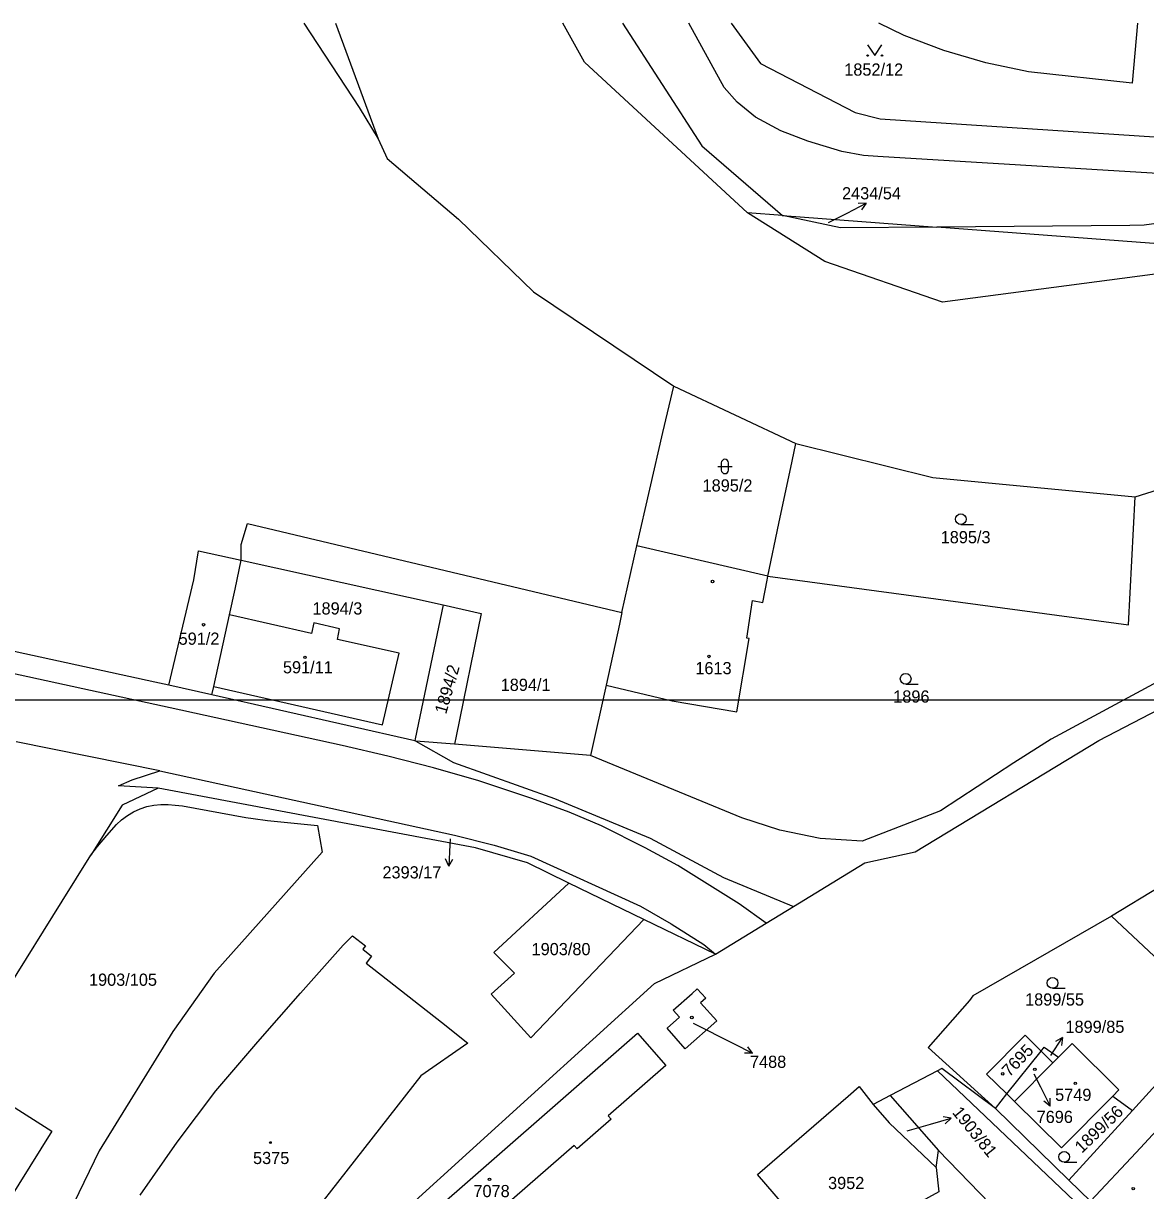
# Model space of a CAD drawing. Extents: x -667048 to -665920, y -1108425 to -1107247.
# Drawn here: x -666539 to -666382.5, y -1107411.8 to -1107249 of the extents above; entities that cross this region are included whole.
import ezdxf

# ---------------------------------------------------------------- set-up
doc = ezdxf.new("R2010")
doc.units = 0
for name, color, linetype in [('Default', 7, 'Continuous'), ('Hranice parcel', 7, 'Continuous'), ('Parcelní čísla', 7, 'Continuous'), ('Pop_ PČ_ popisy', 7, 'Continuous'), ('Vrstva 2', 7, 'Continuous'), ('Značky budov', 7, 'Continuous'), ('Značky kultur', 7, 'Continuous')]:
    doc.layers.add(name, color=color, linetype=linetype)

# ---------------------------------------------------------------- blocks, each defined once
blk = doc.blocks.new('3.041')
at = {"layer": 'Default'}
blk.add_line((8, 0), (1758, 0), dxfattribs=at)
blk.add_circle((8, 750), 750, dxfattribs=at)
blk = doc.blocks.new('4.021')
at = {"layer": 'Default'}
blk.add_circle((-7, 1), 175, dxfattribs=at)
blk = doc.blocks.new('3.161')
at = {"layer": 'Default'}
for p, q in [((-1000, 1000), (1000, 1000)), ((-500, 1500), (-500, 500)), ((500, 500), (500, 1500))]:
    blk.add_line(p, q, dxfattribs=at)
for centre, start, end in [((0, 1500), 0, 180), ((0, 500), 180, 359.98789)]:
    blk.add_arc(centre, 500, start, end, dxfattribs=at)
blk = doc.blocks.new('3.141')
at = {"layer": 'Default'}
blk.add_lwpolyline([(-1000, 1500), (0, 0), (1000, 1500)], dxfattribs=at)
for centre in [(-1000, 0), (1000, 0)]:
    blk.add_circle(centre, 100, dxfattribs=at)
blk = doc.blocks.new('10291')
at = {"layer": 'Default'}
for p, q in [((0, 3001), (-500, 2001)), ((0, 1), (0, 3001)), ((0, 3001), (500, 2001))]:
    blk.add_line(p, q, dxfattribs=at)

msp = doc.modelspace()

# ---------------------------------------------------------------- linework, layer by layer
at = {"layer": 'Hranice parcel'}
for points in [[(-666499.9, -1107248.98), (-666492.15, -1107260.74)], [(-666495.48, -1107248.98), (-666489.54, -1107265.1)], [(-666438.01, -1107275.44), (-666460.74, -1107254.42), (-666463.77, -1107248.98)], [(-666455.44, -1107248.98), (-666444.37, -1107266.08), (-666433.14, -1107275.81)], [(-666356.11, -1107248.98), (-666356.28, -1107250.97), (-666357.81, -1107254.28), (-666361.3, -1107259.67), (-666363.57, -1107262.67), (-666366, -1107265.03), (-666368.53, -1107266.73), (-666371.2, -1107267.99), (-666374.12, -1107268.93), (-666378.04, -1107269.78), (-666380.05, -1107269.97), (-666419.83, -1107267.58), (-666421.83, -1107267.43), (-666424.83, -1107266.88), (-666429.61, -1107265.42), (-666433.36, -1107263.97), (-666436.88, -1107262.08), (-666439.47, -1107259.99), (-666441.27, -1107257.94), (-666446.21, -1107248.98)], [(-666440.27, -1107248.98), (-666436.2, -1107254.59), (-666423.01, -1107261.41), (-666419.51, -1107262.32), (-666380.56, -1107264.87), (-666364.99, -1107248.98)], [(-666383.61, -1107248.98), (-666384.36, -1107257.34), (-666398.82, -1107255.76), (-666404.76, -1107254.5), (-666410.62, -1107252.78), (-666416.15, -1107250.68), (-666419.67, -1107248.98)], [(-666492.15, -1107260.74), (-666489.54, -1107265.1)], [(-666240.48, -1107268.47), (-666267.99, -1107262.05), (-666298.27, -1107263.82), (-666324.76, -1107267.93), (-666375.17, -1107280.18), (-666411.62, -1107277.43)], [(-666489.54, -1107265.1), (-666488.25, -1107267.83)], [(-666227.09, -1107271.48), (-666227.91, -1107279.13), (-666239, -1107270.86), (-666282.86, -1107265.92), (-666341.26, -1107274.38), (-666358.21, -1107280.96), (-666410.8, -1107287.9), (-666427.23, -1107282.22), (-666438.01, -1107275.44)], [(-666488.25, -1107267.83), (-666478.32, -1107276.31), (-666467.85, -1107286.44), (-666448.3, -1107299.6)], [(-666433.14, -1107275.81), (-666438.01, -1107275.44)], [(-666433.14, -1107275.81), (-666411.62, -1107277.43)], [(-666411.62, -1107277.43), (-666425.05, -1107277.51), (-666433.14, -1107275.81)], [(-666380.65, -1107276.85), (-666382.68, -1107277.12), (-666384.67, -1107277.21), (-666411.62, -1107277.43)], [(-666453.46, -1107321.86), (-666449.8, -1107306.06), (-666448.3, -1107299.6)], [(-666448.3, -1107299.6), (-666431.28, -1107307.61)], [(-666435.17, -1107326.12), (-666433.63, -1107318.77), (-666431.79, -1107310.05), (-666431.28, -1107307.61)], [(-666431.28, -1107307.61), (-666412.16, -1107312.35), (-666383.96, -1107315.05)], [(-666518.72, -1107341.34), (-666520.66, -1107340.91), (-666665.94, -1107309.23)], [(-666383.96, -1107315.05), (-666368.4, -1107310.14)], [(-666529.63, -1107342.05), (-666661.48, -1107313.31), (-666665.26, -1107312.36)], [(-666435.17, -1107326.12), (-666384.86, -1107332.9), (-666383.96, -1107315.05)], [(-666421.62, -1107366.12), (-666414.63, -1107364.57), (-666389.01, -1107349.02), (-666368.67, -1107338.48), (-666320.24, -1107322.6), (-666276.14, -1107317.79), (-666222.54, -1107319.87), (-666182.81, -1107329.06)], [(-666508.62, -1107323.9), (-666508.61, -1107321.69), (-666507.76, -1107318.76), (-666455.51, -1107331.17)], [(-666518.72, -1107341.34), (-666515.24, -1107326.63), (-666514.58, -1107322.59), (-666508.62, -1107323.9)], [(-666455.51, -1107331.17), (-666453.46, -1107321.86)], [(-666435.17, -1107326.12), (-666453.46, -1107321.86)], [(-666510.27, -1107331.49), (-666509.46, -1107327.92), (-666508.62, -1107323.9)], [(-666508.62, -1107323.9), (-666480.47, -1107330.1)], [(-666457.74, -1107341.3), (-666448.5, -1107343.5), (-666439.51, -1107345.04), (-666437.77, -1107334.83), (-666438.12, -1107334.77), (-666437.33, -1107329.51), (-666435.88, -1107329.79), (-666435.28, -1107326.67), (-666435.17, -1107326.12)], [(-666480.47, -1107330.1), (-666484.36, -1107348.82), (-666484.42, -1107349.1)], [(-666480.47, -1107330.1), (-666475.16, -1107331.33), (-666478.65, -1107348.43), (-666478.88, -1107349.57)], [(-666455.51, -1107331.17), (-666455.87, -1107332.82), (-666457.74, -1107341.3)], [(-666512.46, -1107341.52), (-666510.27, -1107331.49)], [(-666512.46, -1107341.52), (-666488.91, -1107346.85), (-666486.61, -1107336.84), (-666495.2, -1107334.94), (-666494.93, -1107333.44), (-666498.47, -1107332.63), (-666498.81, -1107334.12), (-666510.27, -1107331.49)], [(-666369.63, -1107335.75), (-666380.22, -1107340.52), (-666395.65, -1107348.85), (-666400.85, -1107352.15), (-666411.11, -1107358.85), (-666421.99, -1107363.1), (-666427.86, -1107362.73), (-666433.48, -1107361.54), (-666438.81, -1107359.82), (-666459.91, -1107351.11)], [(-666439.17, -1107371.82), (-666447.73, -1107366.49), (-666452.28, -1107364.03), (-666458.35, -1107360.96), (-666462.88, -1107359.02), (-666468.08, -1107357.13), (-666475.46, -1107354.68), (-666481.8, -1107352.83), (-666488.15, -1107351.22), (-666494.55, -1107349.73), (-666518.53, -1107344.47), (-666529.63, -1107342.05)], [(-666512.73, -1107342.69), (-666518.72, -1107341.34)], [(-666512.73, -1107342.69), (-666512.68, -1107342.5), (-666512.46, -1107341.52)], [(-666457.74, -1107341.3), (-666459.91, -1107351.11)], [(-666484.42, -1107349.1), (-666512.73, -1107342.69)], [(-666484.25, -1107349.14), (-666484.42, -1107349.1)], [(-666519.98, -1107353.29), (-666539.99, -1107349.21)], [(-666484.25, -1107349.14), (-666478.99, -1107352.13), (-666464.92, -1107357.11), (-666451.58, -1107362.65), (-666441.37, -1107368.14)], [(-666478.88, -1107349.57), (-666484.25, -1107349.14)], [(-666459.91, -1107351.11), (-666478.88, -1107349.57)], [(-666520.2, -1107355.7), (-666525.75, -1107355.38), (-666523.81, -1107354.54), (-666519.98, -1107353.29)], [(-666519.98, -1107353.29), (-666478.88, -1107362.25), (-666473.32, -1107363.63), (-666468.23, -1107365.18), (-666452.91, -1107372.14), (-666448.63, -1107374.62), (-666444.1, -1107377.5), (-666442.47, -1107378.83)], [(-666520.2, -1107355.7), (-666525.2, -1107358.04), (-666529.58, -1107365.05)], [(-666462.94, -1107368.96), (-666468.7, -1107366.12), (-666475.94, -1107364.01), (-666520.2, -1107355.7)], [(-666529.58, -1107365.05), (-666528.65, -1107363.83), (-666527.38, -1107362.27), (-666526, -1107360.78), (-666525.33, -1107360.09), (-666524.5, -1107359.49), (-666523.62, -1107358.97), (-666522.71, -1107358.57), (-666521.79, -1107358.26), (-666520.82, -1107358.06), (-666519.82, -1107357.98), (-666518.83, -1107357.97), (-666517.84, -1107358.06), (-666516.83, -1107358.15), (-666507.97, -1107359.8), (-666506.97, -1107359.94), (-666504.96, -1107360.19), (-666498, -1107360.88), (-666497.35, -1107364.63), (-666512.39, -1107381.51), (-666518.15, -1107389.63), (-666528.43, -1107406.29), (-666531.96, -1107413.61), (-666543.57, -1107432.05)], [(-666355.67, -1107360.62), (-666380.49, -1107369.45), (-666387.22, -1107373.54)], [(-666548.37, -1107395.1), (-666546.36, -1107391.92), (-666541.19, -1107383.65), (-666533.58, -1107371.45), (-666529.58, -1107365.05)], [(-666431.58, -1107372.19), (-666421.62, -1107366.12)], [(-666441.37, -1107368.14), (-666431.58, -1107372.19)], [(-666452.48, -1107374), (-666468.23, -1107390.5), (-666473.76, -1107384.44), (-666470.5, -1107381.49), (-666473.38, -1107378.61), (-666462.94, -1107368.96)], [(-666452.48, -1107374), (-666462.94, -1107368.96)], [(-666435.38, -1107374.51), (-666439.17, -1107371.82)], [(-666435.38, -1107374.51), (-666431.58, -1107372.19)], [(-666387.22, -1107373.54), (-666406.56, -1107384.65), (-666407.05, -1107385.32), (-666412.83, -1107391.86), (-666403.44, -1107400.37)], [(-666387.22, -1107373.54), (-666372.33, -1107387.54)], [(-666442.47, -1107378.83), (-666452.48, -1107374)], [(-666442.47, -1107378.83), (-666435.38, -1107374.51)], [(-666522.72, -1107412.49), (-666517.55, -1107405.08), (-666512.15, -1107397.92), (-666506.3, -1107391.09), (-666500.36, -1107384.28), (-666494.4, -1107377.61), (-666493.1, -1107376.29), (-666491.29, -1107377.68), (-666491.66, -1107378.16), (-666490.44, -1107379.11), (-666491.2, -1107380.09), (-666480.67, -1107388.33), (-666477.03, -1107391.25), (-666483.55, -1107395.84), (-666509.64, -1107429.21)], [(-666529.53, -1107456.78), (-666503.31, -1107429.33), (-666493.96, -1107422.02), (-666451, -1107382.94), (-666442.47, -1107378.83)], [(-666444.56, -1107385.63), (-666442.3, -1107388.17), (-666446.71, -1107392.06), (-666449.22, -1107389.18), (-666447.51, -1107387.65), (-666448.37, -1107386.68), (-666445.73, -1107384.32), (-666445.02, -1107383.7), (-666443.84, -1107385), (-666444.56, -1107385.63)], [(-666490.55, -1107430.26), (-666494.44, -1107425.82), (-666453.35, -1107389.86), (-666449.38, -1107394.36), (-666457.45, -1107401.4), (-666457.02, -1107401.89), (-666461.75, -1107406.01), (-666462.18, -1107405.52), (-666480.66, -1107421.64), (-666480.23, -1107422.13), (-666483.9, -1107425.32), (-666484.32, -1107424.83), (-666490.55, -1107430.26)], [(-666401.83, -1107398.35), (-666404.65, -1107395.59), (-666399.28, -1107390.17), (-666397.07, -1107392.36)], [(-666387.07, -1107398.66), (-666386.2, -1107397.79), (-666392.73, -1107391.32), (-666394.63, -1107393.24)], [(-666401.83, -1107398.35), (-666397.07, -1107392.36)], [(-666397.07, -1107392.36), (-666396.63, -1107391.8), (-666394.63, -1107393.24)], [(-666397.07, -1107392.36), (-666395.4, -1107394.01)], [(-666395.4, -1107394.01), (-666400.75, -1107399.41)], [(-666394.63, -1107393.24), (-666395.4, -1107394.01)], [(-666377.78, -1107393.51), (-666384.3, -1107400.65)], [(-666548.37, -1107395.1), (-666535.01, -1107403.52), (-666550.41, -1107428.19), (-666554.62, -1107425.56), (-666555.3, -1107426.86), (-666555.74, -1107428.37), (-666555.57, -1107429.89), (-666554.86, -1107431.47), (-666554.11, -1107433.22), (-666553.43, -1107435.65), (-666552.96, -1107439), (-666552.81, -1107441.75), (-666552.36, -1107444), (-666551.43, -1107446.41), (-666550.13, -1107448.35), (-666548.82, -1107449.62)], [(-666411.5, -1107395.12), (-666418.13, -1107398.57)], [(-666410.91, -1107394.81), (-666411.5, -1107395.12)], [(-666411.5, -1107395.12), (-666359.1, -1107444.96)], [(-666403.44, -1107400.37), (-666410.91, -1107394.81)], [(-666438.94, -1107424.82), (-666433.13, -1107413.64), (-666436.63, -1107409.59), (-666423.96, -1107398.67), (-666422.41, -1107397.33), (-666420.5, -1107399.81)], [(-666418.13, -1107398.57), (-666420.5, -1107399.81)], [(-666418.13, -1107398.57), (-666411.38, -1107406.25)], [(-666403.44, -1107400.37), (-666401.83, -1107398.35)], [(-666400.75, -1107399.41), (-666401.83, -1107398.35)], [(-666400.75, -1107399.41), (-666394.23, -1107405.88), (-666387.07, -1107398.66)], [(-666387.07, -1107398.66), (-666384.3, -1107400.65)], [(-666420.5, -1107399.81), (-666418.27, -1107402.4), (-666411.67, -1107408.61)], [(-666393.2, -1107410.4), (-666403.44, -1107400.37)], [(-666384.3, -1107400.65), (-666393.2, -1107410.4)], [(-666371.78, -1107410.88), (-666380.93, -1107403.4), (-666383.82, -1107406.51), (-666390.16, -1107413.32)], [(-666411.67, -1107408.61), (-666411.38, -1107406.25)], [(-666411.38, -1107406.25), (-666399.89, -1107418.1)], [(-666411.67, -1107408.61), (-666411.32, -1107412), (-666424.31, -1107419.11), (-666438.94, -1107424.82)], [(-666390.16, -1107413.32), (-666393.2, -1107410.4)]]:
    msp.add_lwpolyline(points, dxfattribs=at)
at = {"layer": 'Pop_ PČ_ popisy'}
for points in [[(-666426.71, -1107276.79), (-666424.11, -1107275.45)], [(-666479.47, -1107362.75), (-666479.52, -1107363.58)], [(-666445.58, -1107388.47), (-666439.98, -1107391.31)], [(-666398.08, -1107395.55), (-666397.14, -1107397.37)], [(-666415.72, -1107403.51), (-666412.49, -1107402.57)]]:
    msp.add_lwpolyline(points, dxfattribs=at)
at = {"layer": 'Vrstva 2'}
msp.add_lwpolyline([(-666838.39, -1107343.37), (-666244.39, -1107343.37), (-666244.39, -1108183.37), (-666838.39, -1108183.37)], close=True, dxfattribs=at)

# ---------------------------------------------------------------- block references
at = {"layer": 'Pop_ PČ_ popisy'}
for p, xscale, yscale, rotation in [((-666424.11, -1107275.45), 0.0010000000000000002, 0.0010000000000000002, -62.99999993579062), ((-666479.52, -1107363.58), 0.0010000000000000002, 0.0010000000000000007, 177.0000000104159), ((-666439.98, -1107391.31), 0.001, 0.0010000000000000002, -117.00000000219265), ((-666395.7, -1107392.99), 0.0010000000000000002, 0.001, -32.99999994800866), ((-666397.14, -1107397.37), 0.0010000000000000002, 0.0010000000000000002, -152.999999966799), ((-666412.49, -1107402.57), 0.001, 0.0010000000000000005, -74.00000000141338)]:
    msp.add_blockref('10291', p, dxfattribs=dict(at, xscale=xscale, yscale=yscale, rotation=rotation))
at = {"layer": 'Značky budov'}
for p, xscale, yscale in [((-666442.87, -1107326.86), 0.0010000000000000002, 0.0010000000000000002), ((-666513.86, -1107332.89), 0.0010000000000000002, 0.0010000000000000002), ((-666499.72, -1107337.44), 0.0010000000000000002, 0.0010000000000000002), ((-666443.37, -1107337.31), 0.0010000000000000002, 0.0010000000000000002), ((-666445.77, -1107387.68), 0.0010000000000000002, 0.0010000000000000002), ((-666402.4, -1107395.55), 0.0010000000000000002, 0.0010000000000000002), ((-666397.92, -1107394.92), 0.0010000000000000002, 0.0010000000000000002), ((-666392.28, -1107396.86), 0.0010000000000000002, 0.0010000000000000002), ((-666504.54, -1107405.13), 0.0006700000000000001, 0.0006700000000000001), ((-666473.99, -1107410.26), 0.0010000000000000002, 0.0010000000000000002), ((-666384.2, -1107411.57), 0.0010000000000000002, 0.0010000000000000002)]:
    msp.add_blockref('4.021', p, dxfattribs=dict(at, xscale=xscale, yscale=yscale))
at = {"layer": 'Značky kultur', "xscale": 0.0010000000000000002, "yscale": 0.0010000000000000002}
for name, p in [('3.141', (-666420.25, -1107253.48)), ('3.161', (-666441.16, -1107311.81)), ('3.041', (-666408.26, -1107318.91)), ('3.041', (-666415.95, -1107341.18)), ('3.041', (-666395.47, -1107383.61)), ('3.041', (-666393.85, -1107407.88))]:
    msp.add_blockref(name, p, dxfattribs=at)

# ---------------------------------------------------------------- texts
at = {"layer": 'Parcelní čísla'}
for s, p in [('1852/12', (-666424.51, -1107256.28)), ('2434/54', (-666424.82, -1107273.54)), ('1895/2', (-666444.27, -1107314.3)), ('1895/3', (-666411.06, -1107321.52)), ('1894/3', (-666498.68, -1107331.46)), ('591/2', (-666517.35, -1107335.68)), ('591/11', (-666502.8, -1107339.67)), ('1613', (-666445.28, -1107339.79)), ('1894/1', (-666472.43, -1107342.12)), ('1896', (-666417.68, -1107343.75)), ('2393/17', (-666488.92, -1107368.28)), ('1903/80', (-666468.12, -1107378.99)), ('1903/105', (-666529.85, -1107383.26)), ('1899/55', (-666399.29, -1107386.02)), ('1899/85', (-666393.66, -1107389.83)), ('7488', (-666437.66, -1107394.71)), ('5749', (-666395.1, -1107399.32)), ('7696', (-666397.68, -1107402.4)), ('5375', (-666506.97, -1107408.13)), ('3952', (-666426.77, -1107411.62)), ('7078', (-666476.23, -1107412.75))]:
    msp.add_text(s, height=1.7, dxfattribs=at).set_placement(p)
for s, rotation, p in [('1894/2', 74, (-666480.04, -1107345.45)), ('7695', 46, (-666401.49, -1107396.05)), ('1903/81', 309, (-666409.54, -1107400.96)), ('1899/56', 44, (-666391.37, -1107406.71))]:
    msp.add_text(s, height=1.7, rotation=rotation, dxfattribs=at).set_placement(p)

doc.saveas('drawing.dxf')
